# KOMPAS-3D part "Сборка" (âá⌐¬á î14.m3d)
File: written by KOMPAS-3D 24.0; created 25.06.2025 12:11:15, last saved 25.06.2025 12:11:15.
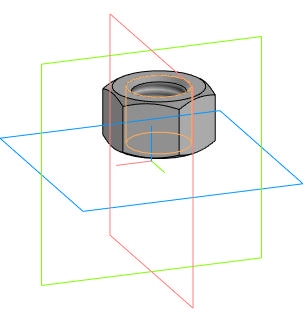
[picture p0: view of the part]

Document properties: Автор: PC321; Полное имя файла: C:\Для ноута\Инженерная графика\ППЭ 2025-2026\Варианты 1-38\Вариант 2 СБ\Решение 2\Вар 2 СБ\Гайка М14.m3d

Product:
- Component [standard]: Гайка М14-6H(S21) ГОСТ 5915-70  | qty 1  | pos. 1  | Масса: 0.02533; Раздел спецификации: Стандартные изделия; Рассекать на разрезах: no; additional columns: М14-6H (S21)
- Part/product: Сборка
    Масса: 0.02533

Referenced files in C:\Program Files\ASCON\KOMPAS-3D v21 Study\Libs\PARTLib\DATA\vault\Methods\Kompas\3D\: PLib_Nut_OST92_900.m3d
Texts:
  bcut1
  hole1
  hcut1
  hole2
  cut1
